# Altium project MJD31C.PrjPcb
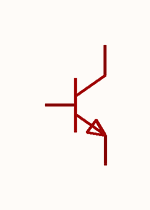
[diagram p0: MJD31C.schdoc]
1 sheet, 1 parts. Net scope: global (net labels, ports and power ports of the same name join across sheets).

## Sheet MJD31C.schdoc
size 127 x 101 mm

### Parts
Q?  mjd31c  [TO-252-3_L6.6-W6.1-P4.57-LS9.9-BR]  (value not drawn)

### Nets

Not connected (* = marked no-connect by the designer): Q? 1(B) 2(E) 3(C)

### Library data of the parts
Q? = mjd31c: 晶体管类型:NPN;集电极电流(Ic):3A;集射极击穿电压(Vceo):100V;耗散功率(Pd):1.25W;直流电流增益(hFE):25;; Manufacturer: CJ(江苏长电/长晶); AddInBom: yes; ModelId: 48edc1c795714fe2bbb2d00a82cae939; ModelTransform: 257.4798,389.763,0,90,0,0,-41.535,0,0; type: NPN; Current - Collector(Ic): 3A; Collector - Emitter Voltage VCEO: 100V; Pd - Power Dissipation: 1.25W; DC Current Gain: 25; Transition frequency(fT): 3MHz; Current - Collector Cutoff: 50uA; Vce Saturation(VCE(sat)): 1.2V; Emitter-Base Voltage(Vebo): 5V; Number: 1个NPN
